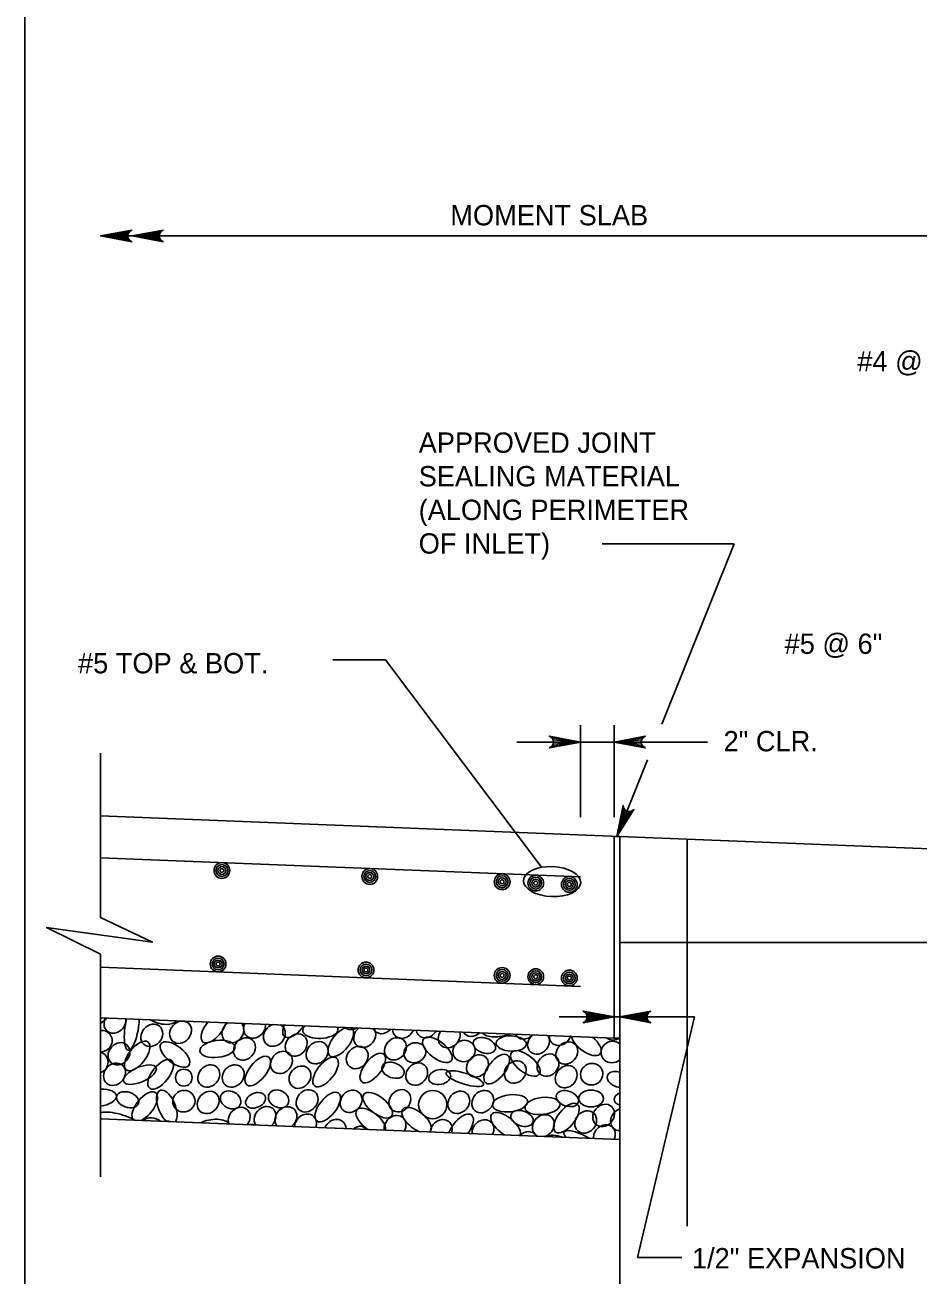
# Model space of a CAD drawing. Extents: x 638167 to 640248, y 296544 to 298920.
# Drawn here: x 639046.8 to 639181.7, y 296656.5 to 296845.2 of the extents above; entities that cross this region are included whole.
import ezdxf

# ---------------------------------------------------------------- set-up
doc = ezdxf.new("R2010")
doc.units = 0
doc.layers.add('1', color=7, linetype='Continuous')
doc.layers.add('50', color=7, linetype='Continuous')

# ---------------------------------------------------------------- blocks, each defined once
blk = doc.blocks.new('BAR')
at = {"layer": '50'}
for radius in [2, 1.5, 1, 0.5]:
    blk.add_circle((0, 0), radius, dxfattribs=at)

msp = doc.modelspace()

# ---------------------------------------------------------------- linework, layer by layer
at = {"layer": '1'}
for p, q in [((639046.78, 297123.48), (639046.78, 296559.48)), ((639198.47, 296813.37), (639058.22, 296813.37)), ((639134, 296766.88), (639153.95, 296766.88)), ((639153.95, 296766.88), (639143.03, 296739.62)), ((639101.27, 296749.37), (639093.33, 296749.37)), ((639124.82, 296718.02), (639101.27, 296749.37)), ((639130.74, 296725.61), (639130.74, 296739.49)), ((639135.82, 296725.61), (639135.82, 296739.49)), ((639121.13, 296736.93), (639149.92, 296736.93)), ((639058.22, 296710.46), (639058.22, 296735.25)), ((639140.88, 296734.27), (639136.24, 296722.69)), ((639058.22, 296725.82), (639198.47, 296720.21)), ((639135.82, 296722.71), (639135.82, 296692.21)), ((639136.67, 296722.68), (639136.67, 296628.84)), ((639146.83, 296722.27), (639146.83, 296663.85)), ((639130.74, 296716.56), (639058.22, 296719.46)), ((639197.63, 296706.66), (639136.67, 296706.66)), ((639058.22, 296671.29), (639058.22, 296704.92)), ((639130.74, 296700.04), (639058.22, 296702.94)), ((639058.22, 296695.31), (639135.82, 296692.21)), ((639127.51, 296695.44), (639147.94, 296695.44)), ((639139.36, 296659.11), (639147.94, 296695.44)), ((639136.67, 296676.92), (639058.22, 296680.06)), ((639146.03, 296659.11), (639139.36, 296659.11))]:
    msp.add_line(p, q, dxfattribs=at)
for points in [[(639058.22, 296813.37), (639062.92, 296812.49), (639062.74, 296812.61), (639062.56, 296812.74), (639062.46, 296812.89), (639062.37, 296813.05), (639062.34, 296813.21), (639062.32, 296813.37), (639062.34, 296813.52), (639062.37, 296813.68), (639062.46, 296813.84), (639062.56, 296814), (639062.74, 296814.12), (639062.92, 296814.25), (639058.22, 296813.37), (639062.74, 296814.12), (639062.56, 296814), (639058.22, 296813.37), (639062.46, 296813.84), (639062.37, 296813.68), (639058.22, 296813.37), (639062.34, 296813.52), (639062.32, 296813.37), (639058.22, 296813.37), (639062.34, 296813.21), (639062.37, 296813.05), (639058.22, 296813.37), (639062.46, 296812.89), (639062.56, 296812.74), (639058.22, 296813.37), (639062.74, 296812.61)], [(639062.97, 296813.37), (639067.66, 296812.49), (639067.48, 296812.61), (639067.3, 296812.74), (639067.21, 296812.89), (639067.12, 296813.05), (639067.09, 296813.21), (639067.06, 296813.37), (639067.09, 296813.52), (639067.12, 296813.68), (639067.21, 296813.84), (639067.3, 296814), (639067.48, 296814.12), (639067.66, 296814.25), (639062.97, 296813.37), (639067.48, 296814.12), (639067.3, 296814), (639062.97, 296813.37), (639067.21, 296813.84), (639067.12, 296813.68), (639062.97, 296813.37), (639067.09, 296813.52), (639067.06, 296813.37), (639062.97, 296813.37), (639067.09, 296813.21), (639067.12, 296813.05), (639062.97, 296813.37), (639067.21, 296812.89), (639067.3, 296812.74), (639062.97, 296813.37), (639067.48, 296812.61)], [(639130.74, 296736.93), (639126.04, 296736.05), (639126.4, 296736.3), (639126.59, 296736.62), (639126.64, 296736.93), (639126.59, 296737.25), (639126.4, 296737.56), (639126.04, 296737.82), (639130.74, 296736.93), (639126.4, 296737.56), (639126.59, 296737.25), (639130.74, 296736.93), (639126.64, 296736.93), (639126.59, 296736.62), (639130.74, 296736.93), (639126.4, 296736.3)], [(639135.82, 296736.93), (639140.52, 296737.82), (639140.16, 296737.56), (639139.97, 296737.25), (639139.91, 296736.93), (639139.97, 296736.62), (639140.16, 296736.3), (639140.52, 296736.05), (639135.82, 296736.93), (639140.16, 296736.3), (639139.97, 296736.62), (639135.82, 296736.93), (639139.91, 296736.93), (639139.97, 296737.25), (639135.82, 296736.93), (639140.16, 296737.56)], [(639136.24, 296722.69), (639137.17, 296727.38), (639137.27, 296726.95), (639137.49, 296726.66), (639137.77, 296726.5), (639138.08, 296726.43), (639138.44, 296726.48), (639138.81, 296726.73), (639136.24, 296722.69), (639138.44, 296726.48), (639138.08, 296726.43), (639136.24, 296722.69), (639137.77, 296726.5), (639137.49, 296726.66), (639136.24, 296722.69), (639137.27, 296726.95)], [(639058.22, 296704.92), (639050.05, 296708.92), (639066.04, 296706.74), (639058.22, 296710.46)], [(639135.82, 296695.44), (639131.12, 296694.56), (639131.3, 296694.68), (639131.48, 296694.81), (639131.58, 296694.96), (639131.67, 296695.12), (639131.7, 296695.28), (639131.72, 296695.44), (639131.7, 296695.59), (639131.67, 296695.75), (639131.58, 296695.91), (639131.48, 296696.07), (639131.3, 296696.19), (639131.12, 296696.32), (639135.82, 296695.44), (639131.3, 296696.19), (639131.48, 296696.07), (639135.82, 296695.44), (639131.58, 296695.91), (639131.67, 296695.75), (639135.82, 296695.44), (639131.7, 296695.59), (639131.72, 296695.44), (639135.82, 296695.44), (639131.7, 296695.28), (639131.67, 296695.12), (639135.82, 296695.44), (639131.58, 296694.96), (639131.48, 296694.81), (639135.82, 296695.44), (639131.3, 296694.68)], [(639136.67, 296695.44), (639141.36, 296696.32), (639141.18, 296696.19), (639141, 296696.07), (639140.91, 296695.91), (639140.82, 296695.75), (639140.79, 296695.59), (639140.76, 296695.44), (639140.79, 296695.28), (639140.82, 296695.12), (639140.91, 296694.96), (639141, 296694.81), (639141.18, 296694.68), (639141.36, 296694.56), (639136.67, 296695.44), (639141.18, 296694.68), (639141, 296694.81), (639136.67, 296695.44), (639140.91, 296694.96), (639140.82, 296695.12), (639136.67, 296695.44), (639140.79, 296695.28), (639140.76, 296695.44), (639136.67, 296695.44), (639140.79, 296695.59), (639140.82, 296695.75), (639136.67, 296695.44), (639140.91, 296695.91), (639141, 296696.07), (639136.67, 296695.44), (639141.18, 296696.19)]]:
    msp.add_lwpolyline(points, dxfattribs=at)
msp.add_lwpolyline([(639136.67, 296692.21), (639135.82, 296692.21), (639135.82, 296722.68), (639136.67, 296722.68)], close=True, dxfattribs=at)
msp.add_circle((639108.4, 296682.19), 2.13, dxfattribs=at)
for centre, major_axis, ratio in [((639126.44, 296715.86), (4.32, -0.19), 0.524991), ((639065.94, 296692.64), (1.2, 1.35), 0.844245), ((639070.3, 296693.12), (1.2, 1.35), 0.844245), ((639060.99, 296689.86), (1.2, 1.35), 0.844245), ((639063.74, 296689.53), (-1.65, -2.1), 0.479042), ((639069.45, 296689.75), (-2.1, 1.65), 0.479042), ((639075.87, 296690.6), (-2.65, -0.32), 0.479042), ((639079.95, 296690.58), (1.2, 1.35), 0.844245), ((639087.77, 296691.18), (1.2, 1.35), 0.844245), ((639090.93, 296690.02), (1.2, 1.35), 0.844245), ((639102.77, 296690.61), (1.2, 1.35), 0.844245), ((639105.69, 296690.02), (-1.57, -0.63), 0.87402), ((639109.1, 296690.46), (-2.1, 1.65), 0.479042), ((639113.14, 296690.28), (-1.58, -0.63), 0.948581), ((639116.22, 296691.12), (1.65, -0.58), 0.646802), ((639120.26, 296691.41), (2.29, -0.09), 0.504072), ((639128.66, 296689.98), (1.2, 1.35), 0.844245), ((639081.96, 296687.26), (-1.65, -2.1), 0.479042), ((639085.54, 296688.55), (1.2, 1.35), 0.844245), ((639092.22, 296687.11), (-1.65, -2.1), 0.479042), ((639097, 296689.3), (1.2, 1.35), 0.844245), ((639099.34, 296687.71), (-1.65, -2.1), 0.479042), ((639115.16, 296688.03), (1.2, 1.35), 0.844245), ((639118.07, 296687.56), (-1.65, -2.1), 0.479042), ((639122.41, 296688.41), (-2.1, 1.65), 0.479042), ((639125.82, 296688.15), (1.2, 1.35), 0.844245), ((639060.32, 296686.77), (1.2, 1.35), 0.844245), ((639064.15, 296686.71), (2.45, 1.04), 0.422273), ((639067.28, 296686.76), (-1.65, -2.1), 0.479042), ((639074.56, 296686.5), (1.2, 1.35), 0.844245), ((639078.25, 296686.51), (1.2, 1.35), 0.844245), ((639088.34, 296686.33), (1.2, 1.35), 0.844245), ((639102.4, 296687.37), (1.65, -0.58), 0.646802), ((639105.98, 296686.79), (1.2, 1.35), 0.844245), ((639109.46, 296686.36), (1.65, 0.33), 0.666084), ((639120.88, 296687.11), (1.2, 1.35), 0.844245), ((639128.57, 296686.4), (1.2, 1.35), 0.844245), ((639132.43, 296686.78), (-1.58, -0.63), 0.948581), ((639070.79, 296686.26), (0, 1.28), 0.982495), ((639113.24, 296686.11), (2.83, -0.91), 0.276285), ((639062.31, 296682.93), (1.65, -0.58), 0.646802), ((639070.79, 296682.7), (-1.58, -0.63), 0.948581), ((639074.47, 296682.51), (1.2, 1.35), 0.844245), ((639077.86, 296682.9), (1.43, -0.74), 0.796199), ((639081.63, 296682.83), (1.44, 0.65), 0.687276), ((639085.11, 296683.05), (1.43, -0.74), 0.796199), ((639089.41, 296682.75), (1.2, 1.35), 0.844245), ((639092.53, 296681.82), (-1.65, -2.1), 0.479042), ((639096.06, 296682.69), (1.2, 1.35), 0.844245), ((639100.09, 296682.09), (-2.1, 1.65), 0.479042), ((639103.43, 296682.76), (1.2, 1.35), 0.844245), ((639112.33, 296682.53), (1.2, 1.35), 0.844245), ((639115.96, 296682.64), (1.2, 1.35), 0.844245), ((639120.09, 296682.39), (-2.65, -0.32), 0.479042), ((639128.75, 296683.09), (1.65, -0.58), 0.646802), ((639132.34, 296683.11), (1.88, 0), 0.671766), ((639125, 296681.99), (-2.65, -0.32), 0.479042), ((639128.6, 296680.15), (-1.65, -2.1), 0.479042), ((639134.23, 296680.55), (1.2, 1.35), 0.844245), ((639121.89, 296680.1), (1.65, -0.58), 0.646802), ((639131.52, 296679.56), (1.2, 1.35), 0.844245)]:
    msp.add_ellipse(centre, major_axis=major_axis, ratio=ratio, dxfattribs=at)
for centre, major_axis, ratio, start_param, end_param in [((639058.43, 296696.37), (-1.65, -2.1), 0.479042, 0.915652, 1.419043), ((639060.38, 296694.65), (1.2, 1.35), 0.844245, 1.832191, 5.661841), ((639062.93, 296693.96), (0.54, 3.56), 0.282192, 1.272438, 5.074018), ((639058.27, 296691.78), (-1.58, -0.63), 0.948581, 1.17834, 4.379632), ((639067.14, 296695.76), (-2.54, 0.83), 0.479042, 1.134534, 3.077998), ((639075.32, 296693.75), (-1.65, -2.1), 0.479042, 4.654487, 8.578689), ((639078.21, 296693.19), (1.2, 1.35), 0.844245, 1.28803, 6.206002), ((639081.48, 296693.9), (1.2, 1.35), 0.844245, 1.890226, 5.603806), ((639084.47, 296692.68), (1.2, 1.35), 0.844245, 0.98036, 6.513671), ((639087.66, 296694.55), (-1.65, -2.1), 0.479042, 5.22643, 8.006746), ((639091.42, 296693.47), (-2.67, -0.09), 0.479042, 5.723588, 9.684852), ((639094.51, 296691.65), (-1.65, -2.1), 0.479042, 3.752737, 9.480439), ((639096.28, 296695.21), (1.2, 1.35), 0.844245, 3.163339, 4.330693), ((639098.13, 296692.51), (1.2, 1.35), 0.844245, 1.391983, 6.102049), ((639100.91, 296694.58), (1.2, 1.35), 0.844245, 2.784532, 4.7095), ((639103.98, 296693.88), (1.2, 1.35), 0.844245, 2.412417, 5.081615), ((639107.53, 296693.97), (1.2, 1.35), 0.844245, 2.558256, 4.935776), ((639110.89, 296692.45), (1.2, 1.35), 0.844245, 1.719443, 5.774589), ((639114.49, 296694.18), (1.2, 1.35), 0.844245, 2.893858, 4.600174), ((639118.35, 296693.72), (-2.65, -0.32), 0.479042, 0.336501, 2.157429), ((639122.39, 296693.76), (1.2, 1.35), 0.844245, 2.81366, 4.680372), ((639124.4, 296691.48), (1.2, 1.35), 0.844245, 1.403953, 6.090078), ((639127.68, 296692.81), (1.2, 1.35), 0.844245, 2.338892, 5.15514), ((639131.61, 296691.51), (-2.1, 1.65), 0.479042, 0.504645, 4.608169), ((639135.54, 296690.13), (-1.58, -0.63), 0.948581, 3.622507, 8.21865), ((639135.73, 296693.56), (-1.58, -0.63), 0.948581, 0.532562, 1.791953), ((639057.66, 296688.54), (-1.58, -0.63), 0.948581, 1.548509, 4.009462), ((639136.46, 296685.98), (1.65, -0.58), 0.646802, 1.673956, 5.058083), ((639057.94, 296683.2), (-2.65, -0.32), 0.479042, 1.619756, 4.548569), ((639064.88, 296681.89), (-1.65, -2.1), 0.479042, 0.745882, 6.204108), ((639068.22, 296681.85), (0.99, -2.48), 0.479042, 0.291356, 5.568983), ((639138.47, 296683.2), (-2.65, -0.32), 0.479042, 5.400085, 7.051426), ((639079.16, 296680.09), (1.2, 1.35), 0.844245, 4.781331, 8.995886), ((639083.06, 296680.21), (1.2, 1.35), 0.844245, 4.581811, 9.195407), ((639086.21, 296680.18), (1.2, 1.35), 0.844245, 4.499037, 9.278181), ((639061.47, 296679.57), (3.41, -1.15), 0.282192, 1.065943, 2.915628), ((639061.47, 296679.57), (3.41, -1.15), 0.282192, 3.557896, 3.688417), ((639066.25, 296678.97), (1.65, -0.58), 0.646802, 1.143407, 2.888454), ((639089.19, 296679.08), (1.2, 1.35), 0.844245, 5.164964, 8.612253), ((639099.03, 296679.72), (-2.1, 1.65), 0.479042, 3.365889, 8.03011), ((639102.7, 296678.85), (1.2, 1.35), 0.844245, 4.978229, 8.798989), ((639105.95, 296679.84), (-2.1, 1.65), 0.479042, 3.015179, 8.38082), ((639109.67, 296678.24), (1.2, 1.35), 0.844245, 5.177267, 8.59995), ((639112.62, 296678.52), (-1.65, -2.1), 0.479042, 1.622154, 5.327836), ((639115.99, 296678.22), (1.2, 1.35), 0.844245, 5.035457, 8.741761), ((639119.41, 296679.06), (-2.1, 1.65), 0.479042, 3.250118, 8.14588), ((639125.12, 296678.98), (1.2, 1.35), 0.844245, 4.099678, 9.677539), ((639136.92, 296679.94), (1.2, 1.35), 0.844245, 0.963188, 3.8008), ((639069.78, 296677.74), (-2.1, 1.65), 0.479042, 5.527073, 5.868925), ((639075.14, 296678.66), (-2.65, -0.32), 0.479042, 3.393449, 5.383666), ((639080.79, 296677.5), (1.2, 1.35), 0.844245, 0.386022, 0.824825), ((639093.62, 296678.27), (1.2, 1.35), 0.844245, 5.536812, 8.240405), ((639096.33, 296676.69), (-1.65, -2.1), 0.479042, 2.834769, 4.115221), ((639122.6, 296676.42), (1.2, 1.35), 0.844245, 5.992587, 7.78463), ((639131.4, 296676.31), (3.16, -1.73), 0.282192, 1.517652, 3.731656), ((639134.33, 296677.45), (1.2, 1.35), 0.844245, 5.061791, 8.715426), ((639127.75, 296675.99), (-2.46, 1.05), 0.479042, 4.810466, 5.958546), ((639134.33, 296677.45), (1.2, 1.35), 0.844245, 5.061791, 5.070205)]:
    msp.add_ellipse(centre, major_axis=major_axis, ratio=ratio, start_param=start_param, end_param=end_param, dxfattribs=at)

# ---------------------------------------------------------------- block references
at = {"layer": '1', "xscale": 0.5953136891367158, "yscale": -0.5953136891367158, "rotation": -97.94234134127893}
for p in [(639076.54, 296717.54), (639098.89, 296716.64), (639118.89, 296715.84), (639123.97, 296715.64), (639129.05, 296715.44), (639075.97, 296703.42), (639098.32, 296702.52), (639118.89, 296701.7), (639123.97, 296701.5), (639129.05, 296701.3)]:
    msp.add_blockref('BAR', p, dxfattribs=at)

# ---------------------------------------------------------------- texts
at = {"layer": '1'}
for s, p in [('MOMENT SLAB', (639111.06, 296814.97)), ('#4 @ 6"', (639172.57, 296792.9)), ('APPROVED JOINT', (639106.28, 296780.62)), ('SEALING MATERIAL', (639106.28, 296775.55)), ('(ALONG PERIMETER', (639106.28, 296770.47)), ('OF INLET)', (639106.28, 296765.4)), ('#5 @ 6"', (639161.58, 296750.25)), ('#5 TOP & BOT.', (639054.8, 296747.31)), ('2" CLR.', (639152.35, 296735.54)), ('1/2" EXPANSION', (639147.58, 296657.45))]:
    msp.add_text(s, height=3.072, rotation=360, dxfattribs=at).set_placement(p)

doc.saveas('drawing.dxf')
